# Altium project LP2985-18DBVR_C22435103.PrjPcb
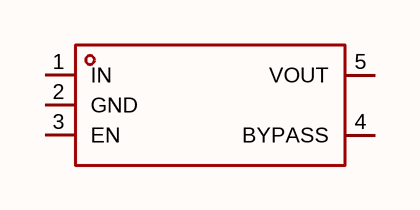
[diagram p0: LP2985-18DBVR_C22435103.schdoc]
1 sheet, 1 parts. Net scope: global (net labels, ports and power ports of the same name join across sheets).

## Sheet LP2985-18DBVR_C22435103.schdoc
size 127 x 101 mm

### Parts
U?  lp2985-18dbvr_c22435103  [SOT-23-5_L3.0-W1.7-P0.95-LS2.8-BR]  (value not drawn)

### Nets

Not connected (* = marked no-connect by the designer): U? 1(IN) 2(GND) 3(EN) 4(BYPASS) 5(VOUT)

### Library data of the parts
U? = lp2985-18dbvr_c22435103: 输出极性:正极;工作电压:18V;输出电压:1.8V;输出电流:150mA;电源纹波抑制比(PSRR):70dB@(1kHz);输出类型:固定;; Manufacturer: TECH PUBLIC(台舟); AddInBom: yes; ModelId: 0a2a1b8f50944f73965918ad6e5fe167; ModelName: SOT-23-5_L2.9-W1.6-H1.1-LS2.8-P0.95; ModelTransform: 114.173,109.636,0,180,0,0,0,0,0; Output Configuration: 正极; Voltage - Supply: 18V; Output Voltage: 1.8V; Output Current: 150mA; Voltage Dropout: 100mV@(100mA); standby current: 10uA; Output Type: 固定; Number of Outputs: 1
